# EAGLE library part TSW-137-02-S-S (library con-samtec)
THROUGH-HOLE .025" SQ POST HEADER Source: Samtec TSW.pdf
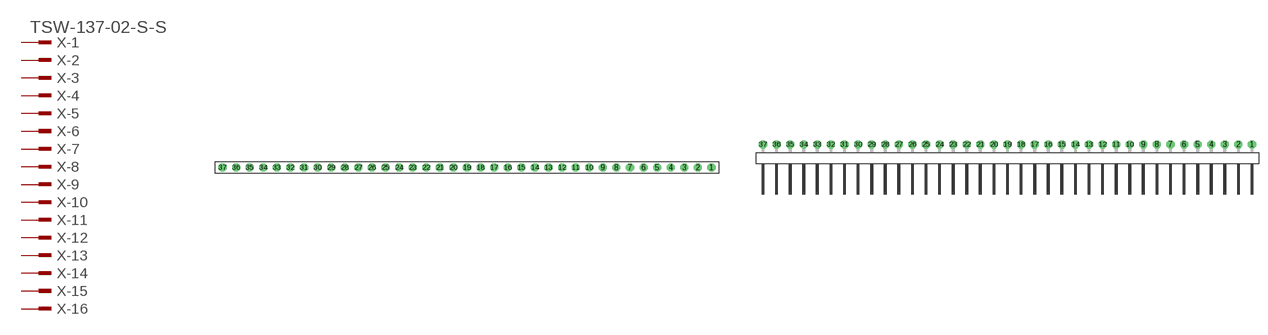
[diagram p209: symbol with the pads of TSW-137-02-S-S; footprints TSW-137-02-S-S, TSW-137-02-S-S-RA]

Designator prefix X; gates -1=MPINV -2=MPIN -3=MPIN -4=MPIN -5=MPIN -6=MPIN -7=MPIN -8=MPIN -9=MPIN -10=MPIN -11=MPIN -12=MPIN -13=MPIN -14=MPIN -15=MPIN -16=MPIN -17=MPIN -18=MPIN -19=MPIN -20=MPIN -21=MPIN -22=MPIN -23=MPIN -24=MPIN -25=MPIN -26=MPIN -27=MPIN -28=MPIN -29=MPIN -30=MPIN -31=MPIN -32=MPIN -33=MPIN -34=MPIN -35=MPIN -36=MPIN -37=MPIN

## TSW-137-02-S-S (OC_FARNELL: unknown; OC_NEWARK: unknown)  [TSW-137-02-S-S]
1  -1:1  pas
2  -2:1  pas
3  -3:1  pas
4  -4:1  pas
5  -5:1  pas
6  -6:1  pas
7  -7:1  pas
8  -8:1  pas
9  -9:1  pas
10  -10:1  pas
11  -11:1  pas
12  -12:1  pas
13  -13:1  pas
14  -14:1  pas
15  -15:1  pas
16  -16:1  pas
17  -17:1  pas
18  -18:1  pas
19  -19:1  pas
20  -20:1  pas
21  -21:1  pas
22  -22:1  pas
23  -23:1  pas
24  -24:1  pas
25  -25:1  pas
26  -26:1  pas
27  -27:1  pas
28  -28:1  pas
29  -29:1  pas
30  -30:1  pas
31  -31:1  pas
32  -32:1  pas
33  -33:1  pas
34  -34:1  pas
35  -35:1  pas
36  -36:1  pas
37  -37:1  pas

## TSW-137-02-S-S-RA (OC_FARNELL: unknown; OC_NEWARK: unknown)  [TSW-137-02-S-S-RA]
Pads as for TSW-137-02-S-S

## Footprint TSW-137-02-S-S (pad centres in mm)
THROUGH-HOLE .025" SQ POST HEADER Source: Samtec TSW.pdf
drill 1 pad 1.5 octagon: 1 45.72,0; 2 43.18,0; 3 40.64,0; 4 38.1,0; 5 35.56,0; 6 33.02,0; 7 30.48,0; 8 27.94,0; 9 25.4,0; 10 22.86,0; 11 20.32,0; 12 17.78,0; 13 15.24,0; 14 12.7,0; 15 10.16,0; 16 7.62,0; 17 5.08,0; 18 2.54,0; 19 0,0; 20 -2.54,0; 21 -5.08,0; 22 -7.62,0; 23 -10.16,0; 24 -12.7,0; 25 -15.24,0; 26 -17.78,0; 27 -20.32,0; 28 -22.86,0; 29 -25.4,0; 30 -27.94,0; 31 -30.48,0; 32 -33.02,0; 33 -35.56,0; 34 -38.1,0; 35 -40.64,0; 36 -43.18,0; 37 -45.72,0

## Footprint TSW-137-02-S-S-RA (pad centres in mm)
THROUGH-HOLE .025" SQ POST HEADER Source: Samtec TSW.pdf
drill 1 pad 1.5 octagon: 1 45.72,1.524; 2 43.18,1.524; 3 40.64,1.524; 4 38.1,1.524; 5 35.56,1.524; 6 33.02,1.524; 7 30.48,1.524; 8 27.94,1.524; 9 25.4,1.524; 10 22.86,1.524; 11 20.32,1.524; 12 17.78,1.524; 13 15.24,1.524; 14 12.7,1.524; 15 10.16,1.524; 16 7.62,1.524; 17 5.08,1.524; 18 2.54,1.524; 19 0,1.524; 20 -2.54,1.524; 21 -5.08,1.524; 22 -7.62,1.524; 23 -10.16,1.524; 24 -12.7,1.524; 25 -15.24,1.524; 26 -17.78,1.524; 27 -20.32,1.524; 28 -22.86,1.524; 29 -25.4,1.524; 30 -27.94,1.524; 31 -30.48,1.524; 32 -33.02,1.524; 33 -35.56,1.524; 34 -38.1,1.524; 35 -40.64,1.524; 36 -43.18,1.524; 37 -45.72,1.524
